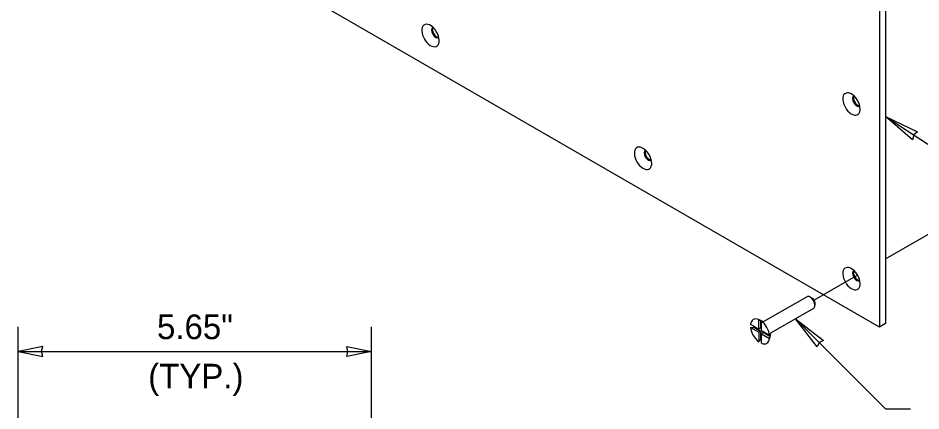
# Model space of a CAD drawing. Extents: x 99862 to 103151, y 100000 to 105076.
# Drawn here: x 101648 to 102234, y 100750 to 101005 of the extents above; entities that cross this region are included whole.
import ezdxf

# ---------------------------------------------------------------- set-up
doc = ezdxf.new("R2010")
doc.units = 0
for name, color, linetype in [('Level 15', 7, 'Continuous'), ('Level 2', 7, 'Continuous'), ('Level 20', 7, 'Continuous')]:
    doc.layers.add(name, color=color, linetype=linetype)

# ---------------------------------------------------------------- blocks, each defined once
blk = doc.blocks.new('T')
at = {"layer": 'Level 15'}
blk.add_lwpolyline([(0, 0), (-22.829, 2.985), (-21.773, 0), (-22.83, -2.985)], close=True, dxfattribs=at)

msp = doc.modelspace()

# ---------------------------------------------------------------- linework, layer by layer
at = {"layer": 'Level 15'}
for p, q in [((102210.9, 100941.29), (102310.82, 100876.12)), ((102192.74, 100838.48), (102164.56, 100822.21)), ((102152.39, 100810.14), (102210.98, 100751.54)), ((101877.31, 100677.95), (101877.31, 100804.93)), ((101648.09, 100788.93), (101877.31, 100788.93)), ((102226.98, 100751.54), (102210.98, 100751.54))]:
    msp.add_line(p, q, dxfattribs=at)
for points in [[(102210.9, 100941.29), (102231.65, 100931.32), (102229.13, 100929.39), (102228.39, 100926.31)], [(102152.39, 100810.14), (102170.65, 100796.1), (102167.79, 100794.74), (102166.42, 100791.88)]]:
    msp.add_lwpolyline(points, close=True, dxfattribs=at)
at = {"layer": 'Level 2'}
for p, q in [((102206.91, 101073.22), (102206.91, 100804.75)), ((102210.9, 101075.52), (102210.9, 100807.05)), ((102206.91, 100804.75), (101762.28, 101061.46)), ((102210.9, 100848.97), (102449.18, 100986.54)), ((102192.74, 100838.48), (102192.74, 100838.48)), ((102131.75, 100808.32), (102159.73, 100824.47)), ((102161.92, 100824.26), (102163.46, 100823.37)), ((102165.01, 100820.69), (102165.01, 100818.9)), ((102164.1, 100816.9), (102136.13, 100800.74)), ((102125.38, 100805.26), (102123.22, 100806.51)), ((102129.2, 100809.35), (102128.5, 100809.63)), ((102128.57, 100809.6), (102129.2, 100809.35)), ((102128.57, 100803.42), (102128.57, 100809.6)), ((102129.77, 100809.12), (102129.77, 100804.11)), ((102129.85, 100809.09), (102131.75, 100808.32)), ((102130.29, 100802.43), (102130.29, 100808.61)), ((102210.9, 100807.05), (102206.91, 100804.75)), ((101648.09, 100686.17), (101648.09, 100804.93)), ((102123.22, 100804.53), (102128.57, 100801.44)), ((102125.38, 100805.26), (102128.57, 100803.42)), ((102125.44, 100804.63), (102129.77, 100802.13)), ((102129.77, 100804.11), (102128.57, 100803.42)), ((102129.77, 100802.13), (102128.57, 100801.44)), ((102128.57, 100801.44), (102128.57, 100795.26)), ((102129.77, 100802.13), (102129.77, 100797.13)), ((102135.65, 100799.34), (102130.29, 100802.43)), ((102131.49, 100801.14), (102130.29, 100800.44)), ((102135.83, 100798.63), (102131.49, 100801.14)), ((102136.13, 100800.74), (102135.84, 100798.71)), ((102130.29, 100796.76), (102130.29, 100800.44)), ((102130.29, 100800.44), (102135.65, 100797.35)), ((102130.29, 100794.26), (102130.29, 100796.76)), ((102135.74, 100798.02), (102135.63, 100797.27)), ((102135.74, 100798.02), (102135.65, 100797.35))]:
    msp.add_line(p, q, dxfattribs=at)
for centre, major_axis, start_param, end_param in [((101915.65, 100993.86), (-3.98, 6.9), 5.621207, 10.086756), ((101915.65, 100993.86), (-3.98, 6.9), 3.926991, 5.621207), ((101919.02, 100995.81), (1.91, -3.31), 3.141593, 6.283185), ((101919.64, 100996.17), (1.91, -3.31), 3.386734, 6.038044), ((101919.02, 100995.81), (1.91, -3.31), 3.074636, 3.141593), ((101919.02, 100995.81), (1.91, -3.31), 0, 0.066956), ((101915.65, 100993.86), (-3.98, 6.9), 3.803571, 3.926991), ((102188.76, 100949.46), (-3.98, 6.9), 5.621207, 10.086756), ((102188.76, 100949.46), (-3.98, 6.9), 3.926991, 5.621207), ((102192.13, 100951.41), (1.91, -3.31), 3.141593, 6.283185), ((102192.75, 100951.76), (1.91, -3.31), 3.386734, 6.038044), ((102192.13, 100951.41), (1.91, -3.31), 3.074636, 3.141593), ((102192.13, 100951.41), (1.91, -3.31), 6.283185, 6.350142), ((102188.76, 100949.46), (-3.98, 6.9), 3.803571, 3.926991), ((102053.54, 100914.26), (-3.98, 6.9), 5.621207, 10.086756), ((102053.54, 100914.26), (-3.98, 6.9), 3.926991, 5.621207), ((102056.91, 100916.2), (1.91, -3.31), 3.141593, 6.283185), ((102057.53, 100916.56), (1.91, -3.31), 3.386734, 6.038044), ((102056.91, 100916.2), (1.91, -3.31), 3.074636, 3.141593), ((102056.91, 100916.2), (1.91, -3.31), 6.283185, 6.350142), ((102053.54, 100914.26), (-3.98, 6.9), 3.803571, 3.926991), ((102188.76, 100836.18), (-3.98, 6.9), 5.621207, 10.086756), ((102188.76, 100836.18), (-3.98, 6.9), 3.926991, 5.621207), ((102192.13, 100838.13), (1.91, -3.31), 3.141593, 6.283185), ((102192.75, 100838.49), (1.91, -3.31), 3.386734, 6.038044), ((102192.13, 100838.13), (1.91, -3.31), 3.074636, 3.141593), ((102192.13, 100838.13), (1.91, -3.31), 6.283185, 6.350142), ((102188.76, 100836.18), (-3.98, 6.9), 3.803571, 3.926991), ((102161.92, 100820.69), (2.19, -3.79), 2.356194, 3.141593), ((102161.92, 100820.69), (2.19, -3.79), 0.785398, 2.356194), ((102163.46, 100821.58), (1.09, -1.89), 0.785398, 2.356194), ((102161.92, 100820.69), (2.19, -3.79), 0, 0.785398), ((102129.43, 100801.93), (4.43, -7.68), 2.506399, 3.789413), ((102129.43, 100801.93), (4.43, -7.68), 2.493773, 2.506399), ((102130.63, 100802.63), (3.72, -6.45), 2.506399, 2.520317), ((102130.63, 100802.63), (3.72, -6.45), 2.192072, 2.506399), ((102129.43, 100801.93), (4.43, -7.68), 0.922976, 2.218616), ((102129.43, 100801.93), (4.43, -7.68), 4.064569, 5.360209), ((102130.63, 100802.63), (3.72, -6.45), 3.991685, 4.091113), ((102130.63, 100802.63), (3.72, -6.45), 0.635193, 0.94952), ((102130.63, 100802.63), (3.72, -6.45), 5.333665, 5.433093), ((102129.43, 100801.93), (4.43, -7.68), 5.635365, 6.918379), ((102129.43, 100801.93), (4.43, -7.68), 0.635193, 0.64782), ((102130.63, 100802.63), (3.72, -6.45), 0.621276, 0.635193)]:
    msp.add_ellipse(centre, major_axis=major_axis, ratio=0.57735, start_param=start_param, end_param=end_param, dxfattribs=at)
for points in [[(102129.2, 100809.35), (102129.39, 100809.27), (102129.58, 100809.2), (102129.77, 100809.12)], [(102130.29, 100808.61), (102130.69, 100808.45), (102131.09, 100808.29), (102131.49, 100808.12)], [(102123.22, 100804.53), (102123.96, 100804.56), (102124.7, 100804.6), (102125.44, 100804.63)], [(102135.83, 100800.62), (102135.77, 100800.19), (102135.71, 100799.77), (102135.65, 100799.34)], [(102129.77, 100797.13), (102129.37, 100796.5), (102128.97, 100795.88), (102128.57, 100795.26)], [(102135.83, 100798.63), (102135.8, 100798.43), (102135.77, 100798.22), (102135.74, 100798.02)]]:
    msp.add_open_spline(points, degree=2, dxfattribs=at)

# ---------------------------------------------------------------- block references
at = {"layer": 'Level 15', "xscale": 0.700832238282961, "yscale": 1.0720268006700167, "rotation": 180}
msp.add_blockref('T', (101648.09, 100788.93), dxfattribs=at)
at = {"layer": 'Level 15', "xscale": 0.700832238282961, "yscale": -1.0720268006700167}
msp.add_blockref('T', (101877.31, 100788.93), dxfattribs=at)

# ---------------------------------------------------------------- texts
at = {"layer": 'Level 20'}
for s, p in [('5.65"', (101738.23, 100796.93)), ('(TYP.)', (101732.52, 100764.93))]:
    msp.add_text(s, height=16, dxfattribs=at).set_placement(p)

doc.saveas('drawing.dxf')
